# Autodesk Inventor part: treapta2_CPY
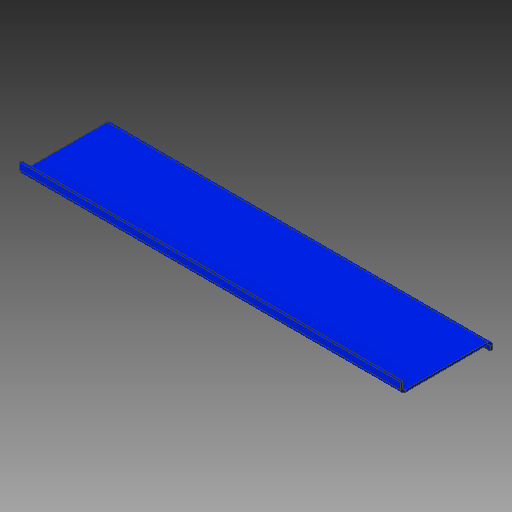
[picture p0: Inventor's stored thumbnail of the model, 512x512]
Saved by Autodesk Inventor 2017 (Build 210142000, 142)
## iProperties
Created: 2017-11
Part Number: treapta2_CPY
Material: Generic
Document SubType Name: Sheet Metal
Designer: iusti
Density: 1 g/cm^3
Sheet Metal Rule: Default_mm
Appearance: Default
Author: iusti
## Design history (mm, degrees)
node "Contour Flange1"
  sketch "Sketch1"
    geometry: L1 (20.807, 182.422)-(0.807, 182.422); L2 (0.807, 182.422)-(0.807, -17.578); L3 (0.807, -17.578)-(-19.193, -17.578); 1 further point
    constraints: 6 end point, 2 perpendicular, 1 horizontal
    dimensions: "d0" = 20 distance of L1.start L1.end; "d1" = 20 distance of L2.end L3.end; "d2" = 200 distance of L1.end L2.end
body "Solid1"
face "Plate1" dims "d3" = 5 (= BendReliefWidth), "d4" = 2.5 (= BendReliefDepth), "d5" = 10 (= MinimumRemnant), "d6" = 5 (= BendRadius), "d7" = 850, "d8" = 5 (= BendRadius), "d9" = 0.5, "d10" = 20 (= CornerReliefSize), "d11" = 5 (= GapSize), "d12" = 5 (= JacobiRadiusSize), "SeamGap" = 0.01, "Thickness" = 5 (derived)
bend "Bend1" dims "d3" = 5 (= BendReliefWidth), "d4" = 2.5 (= BendReliefDepth), "d5" = 10 (= MinimumRemnant), "d6" = 5 (= BendRadius), "d8" = 5 (= BendRadius), "d9" = 0.5, "SeamGap" = 0.01, "Thickness" = 5 (derived)
feature "Corner1" dims "d9" = 0.5, "d10" = 20 (= CornerReliefSize), "d11" = 5 (= GapSize), "d12" = 5 (= JacobiRadiusSize)
other parameters: "BendRadius" = 5 (= Thickness), "BendReliefWidth" = 5 (= Thickness), "BendReliefDepth" = 2.5 (= 0.5 x Thickness), "TransitionRadius" = 5 (= BendRadius), "JacobiRadiusSize" = 5 (= BendRadius), "GapSize" = 5 (= Thickness)
